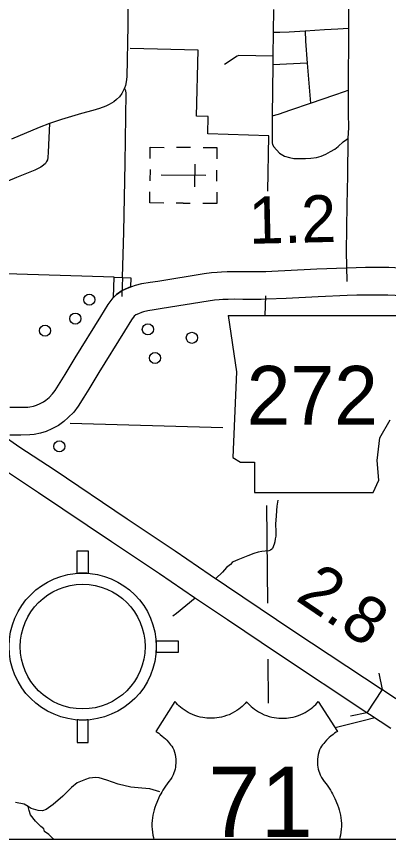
# Model space of a CAD drawing. Extents: x 1382482 to 1385815, y 1168351 to 1170484.
# Drawn here: x 1384395.6 to 1384529.1, y 1168702.4 to 1168998.2 of the extents above; entities that cross this region are included whole.
import ezdxf

# ---------------------------------------------------------------- set-up
doc = ezdxf.new("R2010")
doc.units = 0
for name, color, linetype in [('10', 7, 'Continuous'), ('15', 7, 'Continuous'), ('21', 7, 'Continuous'), ('22', 7, 'Continuous'), ('35', 7, 'Continuous'), ('37', 7, 'Continuous'), ('48', 7, 'Continuous'), ('5', 7, 'Continuous'), ('57', 7, 'Continuous'), ('6', 7, 'Continuous'), ('Default', 7, 'Continuous'), ('R_No Plot', 7, 'Continuous')]:
    doc.layers.add(name, color=color, linetype=linetype)

msp = doc.modelspace()

# ---------------------------------------------------------------- linework, layer by layer
at = {"layer": '10'}
for points in [[(1384393.21, 1168857.69), (1384396.93, 1168857.69), (1384399.67, 1168857.79), (1384400.4, 1168857.86), (1384401.72, 1168858.14), (1384402.76, 1168858.45), (1384404.02, 1168859.02), (1384405.3, 1168859.65), (1384406.14, 1168860.29), (1384407.24, 1168861.27), (1384408.49, 1168862.52), (1384409.4, 1168863.78), (1384411.25, 1168866.67), (1384412.98, 1168869.44), (1384416.61, 1168875.43), (1384425.83, 1168890.37), (1384428.5, 1168894.65), (1384430.21, 1168897.04), (1384431.51, 1168898.26), (1384433.47, 1168899.63), (1384435.39, 1168900.49), (1384436.93, 1168901.11), (1384438.3, 1168901.57), (1384440.56, 1168902.16), (1384443.5, 1168902.67), (1384446.34, 1168903.06), (1384462.91, 1168905.78), (1384465.54, 1168906.12), (1384467.58, 1168906.31), (1384469.21, 1168906.39), (1384471.2, 1168906.46), (1384473.85, 1168906.54), (1384476.92, 1168906.5), (1384480.53, 1168906.5), (1384483.3, 1168906.5), (1384485.05, 1168906.51)], [(1384484.87, 1168906.51), (1384491.93, 1168906.82), (1384503.41, 1168907.42), (1384514, 1168907.87), (1384517.48, 1168907.94), (1384520.85, 1168908.05), (1384525.12, 1168908.05), (1384529.2, 1168908.01), (1384539.72, 1168907.46), (1384547.53, 1168907.11), (1384554.1, 1168906.93), (1384557.15, 1168906.82), (1384563.66, 1168906.54), (1384567.21, 1168906.44), (1384570.95, 1168906.4), (1384577.43, 1168906.23), (1384582.14, 1168906.12), (1384586.38, 1168905.98), (1384591.81, 1168905.76), (1384599.4, 1168905.49), (1384604.12, 1168895.31)], [(1384604.12, 1168895.31), (1384600.17, 1168895.45), (1384591.44, 1168895.77), (1384586.02, 1168895.98), (1384581.86, 1168896.12), (1384577.18, 1168896.23), (1384570.77, 1168896.4), (1384567.02, 1168896.44), (1384563.3, 1168896.55), (1384556.75, 1168896.83), (1384553.79, 1168896.94), (1384547.18, 1168897.11), (1384539.24, 1168897.47), (1384528.89, 1168898.01), (1384525.07, 1168898.05), (1384521.01, 1168898.05), (1384517.74, 1168897.94), (1384514.31, 1168897.87), (1384503.88, 1168897.43), (1384492.41, 1168896.83), (1384485.31, 1168896.52)], [(1384485.13, 1168896.52), (1384483.34, 1168896.5), (1384480.53, 1168896.5), (1384476.86, 1168896.5), (1384473.93, 1168896.53), (1384471.52, 1168896.47), (1384469.63, 1168896.4), (1384468.3, 1168896.33), (1384466.66, 1168896.18), (1384464.35, 1168895.88), (1384447.84, 1168893.17), (1384445.03, 1168892.78), (1384442.67, 1168892.37), (1384441.14, 1168891.98), (1384440.39, 1168891.73), (1384439.32, 1168891.29), (1384438.41, 1168890.89), (1384437.83, 1168890.48), (1384437.78, 1168890.44), (1384436.81, 1168889.08), (1384434.33, 1168885.1), (1384425.14, 1168870.21), (1384421.5, 1168864.2), (1384419.7, 1168861.33), (1384417.66, 1168858.14), (1384416.11, 1168856), (1384414.11, 1168854.01), (1384412.53, 1168852.59), (1384410.61, 1168851.11), (1384408.28, 1168849.97), (1384406.25, 1168849.06), (1384404.19, 1168848.45), (1384401.91, 1168847.95), (1384400.3, 1168847.81), (1384397.11, 1168847.69), (1384393.21, 1168847.69)]]:
    msp.add_lwpolyline(points, dxfattribs=at)
at = {"layer": '15'}
for points in [[(1384521.35, 1168747.9), (1384489.62, 1168768.93), (1384471.27, 1168781.28), (1384459.46, 1168789.26), (1384446.89, 1168797.82), (1384429.71, 1168809.31), (1384403.51, 1168826.99), (1384391.24, 1168835.12), (1384384.33, 1168839.82), (1384380.68, 1168842.21), (1384379.17, 1168843.3), (1384376.45, 1168845.24), (1384370.45, 1168849.65), (1384365.76, 1168853.69), (1384361.43, 1168857.53), (1384357.56, 1168861.51), (1384352.86, 1168866.85), (1384349.01, 1168871.47), (1384344.54, 1168877.59), (1384341.24, 1168883.44), (1384338.06, 1168889.49), (1384334.98, 1168896.09), (1384333.19, 1168900.58), (1384331.32, 1168905.43)], [(1384389.88, 1168848.14), (1384396.81, 1168843.43), (1384409.07, 1168835.3), (1384435.29, 1168817.61), (1384452.48, 1168806.11), (1384465.07, 1168797.54), (1384476.86, 1168789.57), (1384495.17, 1168777.25), (1384526.88, 1168756.23), (1384521.35, 1168747.9)], [(1384535.46, 1168750.55), (1384528.18, 1168755.37), (1384526.88, 1168756.23)], [(1384529.93, 1168742.21), (1384522.3, 1168747.27), (1384521.35, 1168747.9)]]:
    msp.add_lwpolyline(points, dxfattribs=at)
at = {"layer": '21'}
for p, q in [((1384471.54, 1168890.73), (1384474.58, 1168870.43)), ((1384474.58, 1168870.43), (1384473.23, 1168839.64)), ((1384526.01, 1168846.75), (1384529.74, 1168853.18)), ((1384525, 1168838.63), (1384526.01, 1168846.75)), ((1384473.23, 1168839.64), (1384475.94, 1168837.95)), ((1384475.94, 1168837.95), (1384481.01, 1168837.95)), ((1384481.01, 1168837.95), (1384481.01, 1168827.12)), ((1384525.67, 1168831.52), (1384525, 1168838.63)), ((1384523.64, 1168827.12), (1384525.67, 1168831.52)), ((1384481.01, 1168827.12), (1384523.64, 1168827.12))]:
    msp.add_line(p, q, dxfattribs=at)
msp.add_lwpolyline([(1384471.54, 1168890.73), (1384532.39, 1168890.7)], dxfattribs=at)
at = {"layer": '22'}
for points in [[(1384478.18, 1168751.87), (1384477.65, 1168751.28), (1384477.15, 1168750.76), (1384476.58, 1168750.23), (1384475.96, 1168749.7), (1384475.36, 1168749.24), (1384474.64, 1168748.73), (1384473.87, 1168748.25), (1384472.98, 1168747.76), (1384471.86, 1168747.24), (1384471, 1168746.91), (1384470.03, 1168746.59), (1384469.14, 1168746.36), (1384468.32, 1168746.19), (1384467.46, 1168746.06), (1384466.66, 1168745.98), (1384465.57, 1168745.93), (1384464.69, 1168745.94), (1384463.92, 1168745.98), (1384463.19, 1168746.06), (1384462.45, 1168746.17), (1384461.51, 1168746.36), (1384460.65, 1168746.59), (1384459.59, 1168746.93), (1384458.7, 1168747.28), (1384457.89, 1168747.66), (1384457.15, 1168748.04), (1384456.47, 1168748.45), (1384455.7, 1168748.95), (1384455, 1168749.47), (1384454.39, 1168749.96), (1384453.88, 1168750.41), (1384453.36, 1168750.92), (1384452.85, 1168751.45), (1384452.44, 1168751.93), (1384445.52, 1168741.22), (1384446.01, 1168740.93), (1384446.6, 1168740.54), (1384447.16, 1168740.14), (1384447.9, 1168739.57), (1384448.49, 1168739.05), (1384449.02, 1168738.56), (1384449.56, 1168738.02), (1384450.11, 1168737.41), (1384450.5, 1168736.93), (1384450.89, 1168736.43), (1384451.28, 1168735.88), (1384451.67, 1168735.3), (1384452.02, 1168734.62), (1384452.29, 1168733.79), (1384452.49, 1168732.96), (1384452.65, 1168732.07), (1384452.73, 1168731.25), (1384452.76, 1168730.46), (1384452.74, 1168729.72), (1384452.69, 1168729.12), (1384452.59, 1168728.39), (1384452.46, 1168727.71), (1384452.26, 1168726.97), (1384452.05, 1168726.32), (1384451.77, 1168725.58), (1384451.32, 1168724.64), (1384450.86, 1168723.9), (1384450.3, 1168723.23), (1384449.62, 1168722.36), (1384449.07, 1168721.6), (1384448.56, 1168720.83), (1384448.09, 1168720.09), (1384447.69, 1168719.42), (1384447.34, 1168718.79), (1384446.95, 1168718.04), (1384446.54, 1168717.17), (1384446.16, 1168716.31), (1384445.9, 1168715.68), (1384445.59, 1168714.86), (1384445.26, 1168713.86), (1384444.99, 1168713.04), (1384444.74, 1168712.13), (1384444.51, 1168711.08), (1384444.35, 1168710.14), (1384444.24, 1168709.17), (1384444.18, 1168708.1), (1384444.17, 1168707.1), (1384444.22, 1168706.12), (1384444.34, 1168704.97), (1384444.51, 1168703.89), (1384444.69, 1168703.06), (1384444.88, 1168702.36)], [(1384478.18, 1168751.87), (1384478.7, 1168751.28), (1384479.21, 1168750.76), (1384479.78, 1168750.23), (1384480.39, 1168749.7), (1384480.99, 1168749.24), (1384481.71, 1168748.73), (1384482.49, 1168748.25), (1384483.37, 1168747.76), (1384484.49, 1168747.24), (1384485.35, 1168746.91), (1384486.32, 1168746.59), (1384487.21, 1168746.36), (1384488.03, 1168746.19), (1384488.89, 1168746.06), (1384489.69, 1168745.98), (1384490.78, 1168745.93), (1384491.66, 1168745.94), (1384492.43, 1168745.98), (1384493.17, 1168746.06), (1384493.91, 1168746.17), (1384494.84, 1168746.36), (1384495.71, 1168746.59), (1384496.76, 1168746.93), (1384497.65, 1168747.28), (1384498.46, 1168747.66), (1384499.2, 1168748.04), (1384499.89, 1168748.45), (1384500.65, 1168748.95), (1384501.35, 1168749.47), (1384501.96, 1168749.96), (1384502.47, 1168750.41), (1384502.99, 1168750.92), (1384503.5, 1168751.45), (1384503.91, 1168751.93), (1384510.84, 1168741.22), (1384510.34, 1168740.93), (1384509.75, 1168740.54), (1384509.2, 1168740.14), (1384508.45, 1168739.57), (1384507.86, 1168739.05), (1384507.33, 1168738.56), (1384506.8, 1168738.02), (1384506.25, 1168737.41), (1384505.85, 1168736.93), (1384505.46, 1168736.43), (1384505.07, 1168735.88), (1384504.69, 1168735.3), (1384504.33, 1168734.62), (1384504.06, 1168733.79), (1384503.86, 1168732.96), (1384503.71, 1168732.07), (1384503.62, 1168731.25), (1384503.6, 1168730.46), (1384503.62, 1168729.72), (1384503.66, 1168729.12), (1384503.76, 1168728.39), (1384503.9, 1168727.71), (1384504.09, 1168726.97), (1384504.3, 1168726.32), (1384504.58, 1168725.58), (1384505.03, 1168724.64), (1384505.5, 1168723.9), (1384506.05, 1168723.23), (1384506.73, 1168722.36), (1384507.28, 1168721.6), (1384507.79, 1168720.83), (1384508.26, 1168720.09), (1384508.66, 1168719.42), (1384509.01, 1168718.79), (1384509.4, 1168718.04), (1384509.82, 1168717.17), (1384510.19, 1168716.31), (1384510.45, 1168715.68), (1384510.76, 1168714.86), (1384511.1, 1168713.86), (1384511.36, 1168713.04), (1384511.61, 1168712.13), (1384511.85, 1168711.08), (1384512, 1168710.14), (1384512.11, 1168709.17), (1384512.18, 1168708.1), (1384512.18, 1168707.1), (1384512.14, 1168706.12), (1384512.02, 1168704.97), (1384511.84, 1168703.89), (1384511.66, 1168703.06), (1384511.48, 1168702.36)]]:
    msp.add_lwpolyline(points, dxfattribs=at)
at = {"layer": '35'}
for points in [[(1384489.36, 1168824.33), (1384489.05, 1168822.2), (1384488.95, 1168820.61), (1384488.77, 1168818.56), (1384488.53, 1168815.77), (1384488.63, 1168812.91), (1384488.6, 1168811.42), (1384488.38, 1168810.43), (1384488.24, 1168809.34), (1384488.07, 1168808.56), (1384487.82, 1168807.93), (1384487.71, 1168807.57), (1384487.5, 1168806.94), (1384487.25, 1168806.73), (1384486.76, 1168806.37), (1384486.12, 1168806.16), (1384484.85, 1168806.05), (1384483.65, 1168805.88), (1384482.28, 1168805.6), (1384480.79, 1168805.14), (1384478.6, 1168804.32), (1384476.24, 1168803.41), (1384475.02, 1168802.89), (1384473.29, 1168802.19), (1384473.01, 1168801.91), (1384472.34, 1168801.23), (1384470.89, 1168800.14), (1384469.48, 1168798.48), (1384467.14, 1168796.14)], [(1384459.73, 1168789.07), (1384452.95, 1168783.54), (1384451.73, 1168782.66)], [(1384524.14, 1168746.05), (1384519.99, 1168744.97), (1384510.01, 1168742.5)], [(1384446.96, 1168719.51), (1384443.4, 1168720.61), (1384440.59, 1168720.78), (1384436.55, 1168721.15), (1384432.07, 1168722.29), (1384427.99, 1168723.68), (1384425.23, 1168724.51), (1384423.98, 1168724.66), (1384421.67, 1168724.44), (1384420.31, 1168723.94), (1384417.3, 1168722.72), (1384415.25, 1168721.05), (1384412.18, 1168717.92), (1384408.78, 1168714.95), (1384406.25, 1168713.12), (1384404.84, 1168712.69), (1384403.33, 1168712.79), (1384400.8, 1168713.55), (1384399.77, 1168714.2), (1384398.27, 1168715.06), (1384395.25, 1168715.65)], [(1384409.23, 1168702.36), (1384408.78, 1168702.57), (1384407.17, 1168704.17), (1384405.61, 1168705.24), (1384405.37, 1168706.17), (1384404.25, 1168707.05), (1384402.4, 1168708.94), (1384400.55, 1168711.28), (1384400.06, 1168712.79), (1384399.77, 1168714.2)]]:
    msp.add_lwpolyline(points, dxfattribs=at)
at = {"layer": '37'}
for points in [[(1384525.68, 1168762.11), (1384526.88, 1168756.23)], [(1384521.35, 1168747.9), (1384515.47, 1168746.7)]]:
    msp.add_lwpolyline(points, dxfattribs=at)
at = {"layer": '5'}
for points in [[(1384469.64, 1168850.37), (1384414.85, 1168851.91)], [(1384485.32, 1168822.41), (1384485.63, 1168787.32)], [(1384485.8, 1168767.2), (1384485.94, 1168751.42)]]:
    msp.add_lwpolyline(points, dxfattribs=at)
at = {"layer": '57'}
for p, q in [((1384458.03, 1168951.03), (1384453.03, 1168951.07)), ((1384459.53, 1168945.02), (1384459.47, 1168936.98)), ((1384443.51, 1168943.11), (1384443.48, 1168939.11)), ((1384467.48, 1168938.94), (1384467.51, 1168942.94)), ((1384463.5, 1168940.99), (1384447.5, 1168941.1)), ((1384455.5, 1168941.05), (1384455.5, 1168941.05)), ((1384455.5, 1168941.05), (1384455.5, 1168941.05)), ((1384455.42, 1168931.05), (1384452.89, 1168931.07)), ((1384455.42, 1168931.05), (1384457.89, 1168931.03)), ((1384417.32, 1168798.01), (1384417.32, 1168806.09)), ((1384417.32, 1168806.09), (1384421.32, 1168806.09)), ((1384453.72, 1168773.69), (1384445.65, 1168773.69)), ((1384453.72, 1168769.69), (1384453.72, 1168773.69)), ((1384421.32, 1168737.29), (1384421.32, 1168745.36)), ((1384417.32, 1168737.29), (1384421.32, 1168737.29))]:
    msp.add_line(p, q, dxfattribs=at)
for points in [[(1384443.54, 1168947.13), (1384443.57, 1168951.13), (1384448.57, 1168951.1)], [(1384467.54, 1168946.96), (1384467.57, 1168950.96), (1384462.57, 1168951)], [(1384448.43, 1168931.1), (1384443.43, 1168931.13), (1384443.45, 1168935.13)], [(1384467.45, 1168934.96), (1384467.42, 1168930.96), (1384462.42, 1168931)], [(1384421.32, 1168806.09), (1384421.32, 1168798.01), (1384421.05, 1168798.03), (1384420.78, 1168798.05), (1384420.51, 1168798.06), (1384420.18, 1168798.07), (1384419.88, 1168798.08), (1384419.51, 1168798.09), (1384419.28, 1168798.09), (1384418.95, 1168798.08), (1384418.64, 1168798.08), (1384418.36, 1168798.07), (1384418.04, 1168798.05), (1384417.78, 1168798.04), (1384417.55, 1168798.03), (1384417.32, 1168798.01)], [(1384445.65, 1168773.69), (1384445.65, 1168773.59), (1384445.66, 1168773.46), (1384445.67, 1168773.35), (1384445.68, 1168773.25), (1384445.68, 1168773.11), (1384445.69, 1168773), (1384445.7, 1168772.86), (1384445.7, 1168772.76), (1384445.71, 1168772.61), (1384445.71, 1168772.49), (1384445.71, 1168772.37), (1384445.72, 1168772.22), (1384445.72, 1168772.09), (1384445.72, 1168771.97), (1384445.72, 1168771.83), (1384445.72, 1168771.69), (1384445.72, 1168771.54), (1384445.72, 1168771.38), (1384445.72, 1168771.22), (1384445.71, 1168771.01), (1384445.71, 1168770.8), (1384445.7, 1168770.67), (1384445.7, 1168770.5), (1384445.69, 1168770.31), (1384445.67, 1168770.08), (1384445.66, 1168769.9), (1384445.65, 1168769.69), (1384453.72, 1168769.69)], [(1384421.32, 1168745.36), (1384421.19, 1168745.35), (1384421.02, 1168745.34), (1384420.81, 1168745.33), (1384420.55, 1168745.31), (1384420.33, 1168745.31), (1384420.1, 1168745.3), (1384419.87, 1168745.29), (1384419.67, 1168745.29), (1384419.37, 1168745.29), (1384419.02, 1168745.29), (1384418.73, 1168745.29), (1384418.44, 1168745.3), (1384418.2, 1168745.31), (1384417.87, 1168745.33), (1384417.64, 1168745.34), (1384417.32, 1168745.36), (1384417.32, 1168737.29)]]:
    msp.add_lwpolyline(points, dxfattribs=at)
for radius in [26.4, 22.4]:
    msp.add_circle((1384419.32, 1168771.69), radius, dxfattribs=at)
at = {"layer": '6'}
for points in [[(1384485.77, 1168935.32), (1384486.18, 1168955.3), (1384464.25, 1168955.93), (1384464.38, 1168962.15), (1384460.12, 1168962.27), (1384460.74, 1168986), (1384436.36, 1168986.67)], [(1384430.64, 1168904.44), (1384380.02, 1168905.98), (1384380.78, 1168888.51)], [(1384484.87, 1168890.73), (1384485.01, 1168897.75)]]:
    msp.add_lwpolyline(points, dxfattribs=at)
at = {"layer": 'Default'}
msp.add_line((1384430.65, 1168904.47), (1384436.64, 1168904.23), dxfattribs=at)
for points in [[(1384435.47, 1169006.8), (1384435.47, 1168994.91), (1384435.15, 1168976.51), (1384434.92, 1168974.63), (1384434.65, 1168973.4), (1384434.33, 1168972.38), (1384433.41, 1168970.46), (1384432.49, 1168969.23), (1384431.44, 1168968.31), (1384430.48, 1168967.53), (1384428.78, 1168966.48), (1384427.68, 1168965.93), (1384425.39, 1168965.05), (1384422.91, 1168964.32), (1384418.88, 1168963.31), (1384411.73, 1168961.11), (1384407.45, 1168959.71), (1384403.65, 1168958.25), (1384393.79, 1168954.12)], [(1384514.78, 1169007.11), (1384514.75, 1168993.96), (1384514.66, 1168971.64), (1384514.65, 1168969.45), (1384514.59, 1168963.28), (1384514.71, 1168958.3), (1384514.56, 1168954.28), (1384514.37, 1168940.95), (1384514.19, 1168930.41), (1384513.88, 1168913.71), (1384514.16, 1168902.87)], [(1384487.83, 1169000.68), (1384487.67, 1168992.54), (1384487.61, 1168983.92), (1384487.58, 1168980.78), (1384487.33, 1168962.43), (1384487.33, 1168955.37), (1384487.3, 1168952.8), (1384487.49, 1168952.12), (1384487.98, 1168951.28), (1384490.02, 1168949.03), (1384491.72, 1168948.01), (1384493.51, 1168947.45), (1384495.15, 1168947.17), (1384497.22, 1168947.14), (1384499.36, 1168947.14), (1384501.22, 1168947.2), (1384503.26, 1168947.48), (1384504.9, 1168947.98), (1384506.6, 1168948.72), (1384508.26, 1168949.65), (1384509.78, 1168950.51), (1384511.02, 1168951.47), (1384512.87, 1168953.14), (1384514.01, 1168953.97), (1384514.56, 1168954.28)], [(1384487.67, 1168992.54), (1384490.11, 1168992.49), (1384493.48, 1168992.62), (1384499.13, 1168992.96), (1384506.1, 1168993.49), (1384510.89, 1168993.76), (1384514.75, 1168993.96)], [(1384499.13, 1168992.96), (1384499.31, 1168989.28), (1384499.94, 1168981.4), (1384501.08, 1168967.04)], [(1384487.61, 1168983.92), (1384475.39, 1168984.07), (1384474.8, 1168983.9), (1384470.19, 1168980.87)], [(1384499.94, 1168981.4), (1384487.58, 1168980.78)], [(1384433.64, 1168904.35), (1384434.09, 1168920.7), (1384434.58, 1168945.39), (1384434.9, 1168970.61), (1384434.83, 1168971.49), (1384434.33, 1168972.38)], [(1384487.33, 1168962.43), (1384489.64, 1168962.99), (1384494, 1168964.56), (1384501.08, 1168967.04), (1384509.78, 1168969.97), (1384513.36, 1168971.15), (1384514.66, 1168971.64)], [(1384407.45, 1168959.71), (1384406.97, 1168949.33), (1384406.78, 1168947.52), (1384406.63, 1168946.68), (1384406.36, 1168946), (1384405.94, 1168945.29), (1384405.29, 1168944.68), (1384404.29, 1168944), (1384402.14, 1168942.95), (1384397.94, 1168941.3), (1384395.55, 1168940.25), (1384392.48, 1168938.99)], [(1384430.36, 1168897.17), (1384430.65, 1168904.47)], [(1384436.64, 1168904.23), (1384436.51, 1168900.98), (1384433.47, 1168899.63), (1384431.51, 1168898.26), (1384430.36, 1168897.17)], [(1384433.64, 1168904.35), (1384433.4, 1168898.15), (1384433.4, 1168897.48)]]:
    msp.add_lwpolyline(points, dxfattribs=at)
for centre in [(1384421.71, 1168896.36), (1384416.7, 1168889.58), (1384405.8, 1168885.25), (1384442.73, 1168885.72), (1384458.52, 1168882.67), (1384445.28, 1168875.41), (1384410.92, 1168843.67)]:
    msp.add_circle(centre, 2, dxfattribs=at)
at = {"layer": 'R_No Plot'}
msp.add_lwpolyline([(1383432.46, 1169579.7), (1384939.88, 1169579.7), (1384939.88, 1168702.36), (1383432.46, 1168702.36)], close=True, dxfattribs=at)

# ---------------------------------------------------------------- texts
at = {"layer": '21'}
msp.add_text('272', height=21.12, dxfattribs=at).set_placement((1384478.19, 1168851.45))
at = {"layer": '22'}
msp.add_text('71', height=25.344, dxfattribs=at).set_placement((1384464.31, 1168703.22))
at = {"layer": '48'}
for s, rotation, p in [('1.2', 1.3191, (1384479.11, 1168916.44)), ('2.8', 325.8304, (1384495.33, 1168788.65))]:
    msp.add_text(s, height=16.896, rotation=rotation, dxfattribs=at).set_placement(p)

doc.saveas('drawing.dxf')
